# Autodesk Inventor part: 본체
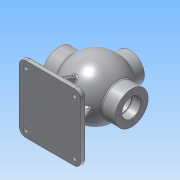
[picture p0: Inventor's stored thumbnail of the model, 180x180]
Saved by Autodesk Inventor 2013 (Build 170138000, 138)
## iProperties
Created: 2018-06
Part Number: 본체
Material: 알루미늄 6061
Document SubType Name: Modeling
Designer: Administrator
Density: 2.71 g/cm^3
Mass: 1509.57 g
Surface Area: 1153.7 cm^2
Volume: 557.037 cm^3
Author: Administrator
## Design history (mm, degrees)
sketch "스케치1"
  geometry: L1 (-68, 31)-(-68, 17.5); L2 (68, 31)-(68, 17.5); L3 (-68, 31)-(-42.988, 31); L4 (42.988, 31)-(68, 31); L5 (-68, 17.5)-(-39.278, 17.5); L6 (39.278, 17.5)-(68, 17.5); L7 (-102.458, 0)-(110.58, 0); A1 r 53 centre (0, 0) between (42.988, 31) and (-42.988, 31); A2 r 43 centre (0, 0) between (39.278, 17.5) and (-39.278, 17.5); 1 further point
  constraints: 14 end point, 6 parallel, 4 point on circle, 2 centre point, 2 coincident, 2 horizontal, 2 perpendicular
  dimensions: "d0" = 106 diameter of A1; "d1" = 86 diameter of A2; "d2" = 136 distance of L1.start L2.start; "d3" = 31 vertical distance of A2.centre L1.start; "d5" = 68 distance from line of L1 point (0, 0); "d6" = 17.5 distance from line of point (0, 0) L5; "d7" = 17.5 distance from line of point (0, 0) L6; "d8" = 31 distance from line of point (0, 0) L4; "d10" = 0 distance from line of L7 point (0, 0)
revolve "회전1" sketch "스케치1" stored, may be unused: angle "d11" = 90 deg
node "작업 평면1"
sketch "스케치3"
  geometry: C1 r 27 at (0, 0); 1 further point
  constraints: 1 centre point, 1 coincident
  dimensions: "d13" = 54 diameter of C1
extrude "돌출1" join sketch "스케치3" stored distance "d14" = 10; taper "d15" = 0 deg
sketch "스케치4"
  geometry: C1 r 27 at (0, 0) reference; C2 r 13 at (0, 0)
  constraints: 1 centre point, 1 coincident
  dimensions: "d16" = 26 diameter of C2
extrude "돌출2" cut sketch "스케치4" stored distance "d17" = 10; taper "d18" = 0 deg
sketch "스케치7"
  geometry: C1 r 13 at (0, 0) reference; 1 further point
  constraints: 1 vertical alignment
  dimensions: "d20" = 20 distance of point (0, 20) C1.centre
hole "구멍1" sketch "스케치7" at (0, 20) diameter "d21" = 3.242; stored, may be unused: countersink angle "d25" = 90 deg, drill point angle "d27" = 118 deg; dims "d22" = 9, "d23" = 4, "d24" = 2, "d26" = 11
sketch "스케치8"
  geometry: C1 r 17.5 at (0, 0) reference; 1 further point
  constraints: 1 vertical alignment
  dimensions: "d31" = 24 distance of C1.centre point (0, 24)
hole "구멍2" sketch "스케치8" at (0, 24) diameter "d32" = 3.242; stored, may be unused: countersink angle "d36" = 90 deg, drill point angle "d38" = 118 deg; dims "d33" = 16, "d34" = 4, "d35" = 2, "d37" = 19
sketch "스케치9"
  geometry: C1 r 31 at (0, 0) reference; 1 further point
  constraints: 1 vertical alignment
  dimensions: "d42" = 22.5 distance of C1.centre point (0, 22.5)
hole "구멍3" sketch "스케치9" at (0, 22.5) diameter "d43" = 3.242; stored, may be unused: countersink angle "d47" = 90 deg, drill point angle "d49" = 118 deg; dims "d44" = 12, "d45" = 4, "d46" = 2, "d48" = 15
node "작업 평면2"
sketch "스케치10"
  geometry: L1 (-57.5, 62.5)-(57.5, 62.5); L2 (57.5, 62.5)-(57.5, -62.5); L3 (57.5, -62.5)-(-57.5, -62.5); L4 (-57.5, -62.5)-(-57.5, 62.5); L5 (-57.5, 62.5)-(57.5, -62.5); L6 (57.5, 62.5)-(-57.5, -62.5); 1 further point
  constraints: 12 end point, 2 midpoint, 2 parallel, 1 horizontal, 1 perpendicular
  dimensions: "d54" = 115 distance of L2.end L3.end; "d55" = 125 distance of L1.end L2.end
extrude "돌출3" join sketch "스케치10" distance "d56" = 10; taper "d57" = 0 deg
sketch "스케치11"
  geometry: L1 (57.5, 62.5)-(-57.5, 62.5) reference; L2 (4, -52.5)-(-4, -52.5); L3 (-4, -52.5)-(-4, 52.5); L4 (-4, 52.5)-(4, 52.5); L5 (4, 52.5)-(4, -52.5); L6 (4, -52.5)-(-4, 52.5); L7 (-4, -52.5)-(4, 52.5); 1 further point
  constraints: 12 end point, 2 midpoint, 2 parallel, 1 horizontal, 1 perpendicular
  dimensions: "d58" = 8 distance of L3.end L4.end; "d61" = 10 distance between parallel lines of L1 L4
extrude "돌출4" join sketch "스케치11" stored distance "d62" = 10; taper "d63" = 0 deg
feature "면 기울기1" dims angle "d64" = 22 deg
sketch "스케치12"
  geometry: L1 (47.5, -75)-(41.456, -60.04); L2 (57.5, -75)-(-57.5, -75) reference; L3 (57.5, -85)-(57.5, -75) reference; 1 further point
  constraints: 2 end point, 1 point on line
  dimensions: "d65" = 10 distance from line of L3 L1.start; "d66" = 22 deg angle of L1 L3
feature "리브1" sketch "스케치12" dims "d67" = 1, "d68" = 8, "d69" = 0, "d70" = 0, "d71" = 1, "d72" = 1
node "작업 평면3"
sketch "스케치15"
  geometry: C1 r 18.5 at (0, 0); 1 further point
  constraints: 1 centre point, 1 coincident
  dimensions: "d93" = 37 diameter of C1
extrude "돌출5" cut sketch "스케치15" distance "d94" = 1.75; taper "d95" = 0 deg
fillet "모깎기1" dims "d96" = 12
node "작업 평면4"
sketch "스케치16"
  geometry: L1 (-27, 45.607)-(27, 45.607) reference; L2 (-27, 65)-(27, 65) reference; L3 (-27, 65)-(-27, 45.607) reference; L4 (-27, 65)-(-27, 45.607) reference; 2 further points
  constraints: 1 other
  dimensions: "d98" = 27 distance from line of L3 point (0, 55); "d99" = 10 distance from line of point (0, 55) L2
feature "엠보싱1" sketch "스케치16" dims "d0" = 106, "d1" = 86, "d2" = 136, "d3" = 31, "d5" = 68, "d6" = 17.5, "d7" = 17.5, "d8" = 31, "d10" = 0, "d100" = 0.5, "d101" = 0
fillet "모깎기2" dims "d102" = 3
fillet "모깎기3" dims "d103" = 3
chamfer "모따기1" distance "d104" = 1; stored, may be unused: second distance "d105" = 2, angle "d106" = 45 deg
sketch "스케치17"
  geometry: A1 r 9 centre (-45.5, -50.5) between (-54.5, -50.5) and (-45.5, -59.5) reference; A2 r 9 centre (45.5, -50.5) between (45.5, -59.5) and (54.5, -50.5) reference; A3 r 9 centre (45.5, 50.5) between (54.5, 50.5) and (45.5, 59.5) reference; A4 r 9 centre (-45.5, 50.5) between (-45.5, 59.5) and (-54.5, 50.5) reference; 5 further points
  constraints: 4 coincident
hole "구멍5" sketch "스케치17" at (-45.5, 50.5), (45.5, 50.5), (-45.5, -50.5), (45.5, -50.5) diameter "d109" = 8; stored, may be unused: countersink angle "d113" = 90 deg, drill point angle "d115" = 0 deg; dims "d110" = 10, "d111" = 12, "d112" = 3, "d114" = 10
sketch "스케치18"
  geometry: L1 (1, 54.524)-(-1, 54.524) reference; L2 (7, 7)-(7, 48.052) reference; L3 (43.052, 7)-(7, 7) reference; L4 (49.524, -1)-(49.524, 1) reference; L5 (7, -7)-(43.052, -7) reference; L6 (7, -48.052)-(7, -7) reference; L7 (-1, -54.524)-(1, -54.524) reference; L8 (-7, -7)-(-7, -48.052) reference; L9 (-43.052, -7)-(-7, -7) reference; L10 (-49.524, 1)-(-49.524, -1) reference; L11 (-7, 7)-(-43.052, 7) reference; L12 (-7, 48.052)-(-7, 7) reference; L13 (45.5, -59.5)-(-45.5, -59.5) reference; L14 (54.5, 50.5)-(54.5, -50.5) reference; L15 (-45.5, 59.5)-(45.5, 59.5) reference; L16 (-54.5, -50.5)-(-54.5, 50.5) reference; C1 r 6 at (-45.5, -50.5) reference; C2 r 6 at (-45.5, 50.5) reference; C3 r 6 at (45.5, 50.5) reference; C4 r 6 at (45.5, -50.5) reference; A1 r 9 centre (-45.5, -50.5) between (-54.5, -50.5) and (-45.5, -59.5) reference; A2 r 9 centre (45.5, -50.5) between (45.5, -59.5) and (54.5, -50.5) reference; A3 r 9 centre (45.5, 50.5) between (54.5, 50.5) and (45.5, 59.5) reference; A4 r 9 centre (-45.5, 50.5) between (-45.5, 59.5) and (-54.5, 50.5) reference; 9 further points; 8 other entities
  constraints: 8 other
node "솔리드1"
pattern_circular "원형 패턴1" dims angle "d29" = 360 deg
pattern_circular "원형 패턴2" dims angle "d40" = 360 deg
pattern_circular "원형 패턴3" dims angle "d51" = 360 deg
mirror "대칭1"
node "투영된 루프1"
other parameters: "d4" = 17.5, "d12" = 65, "d53" = -85, "d92" = -16, "d97" = -27
